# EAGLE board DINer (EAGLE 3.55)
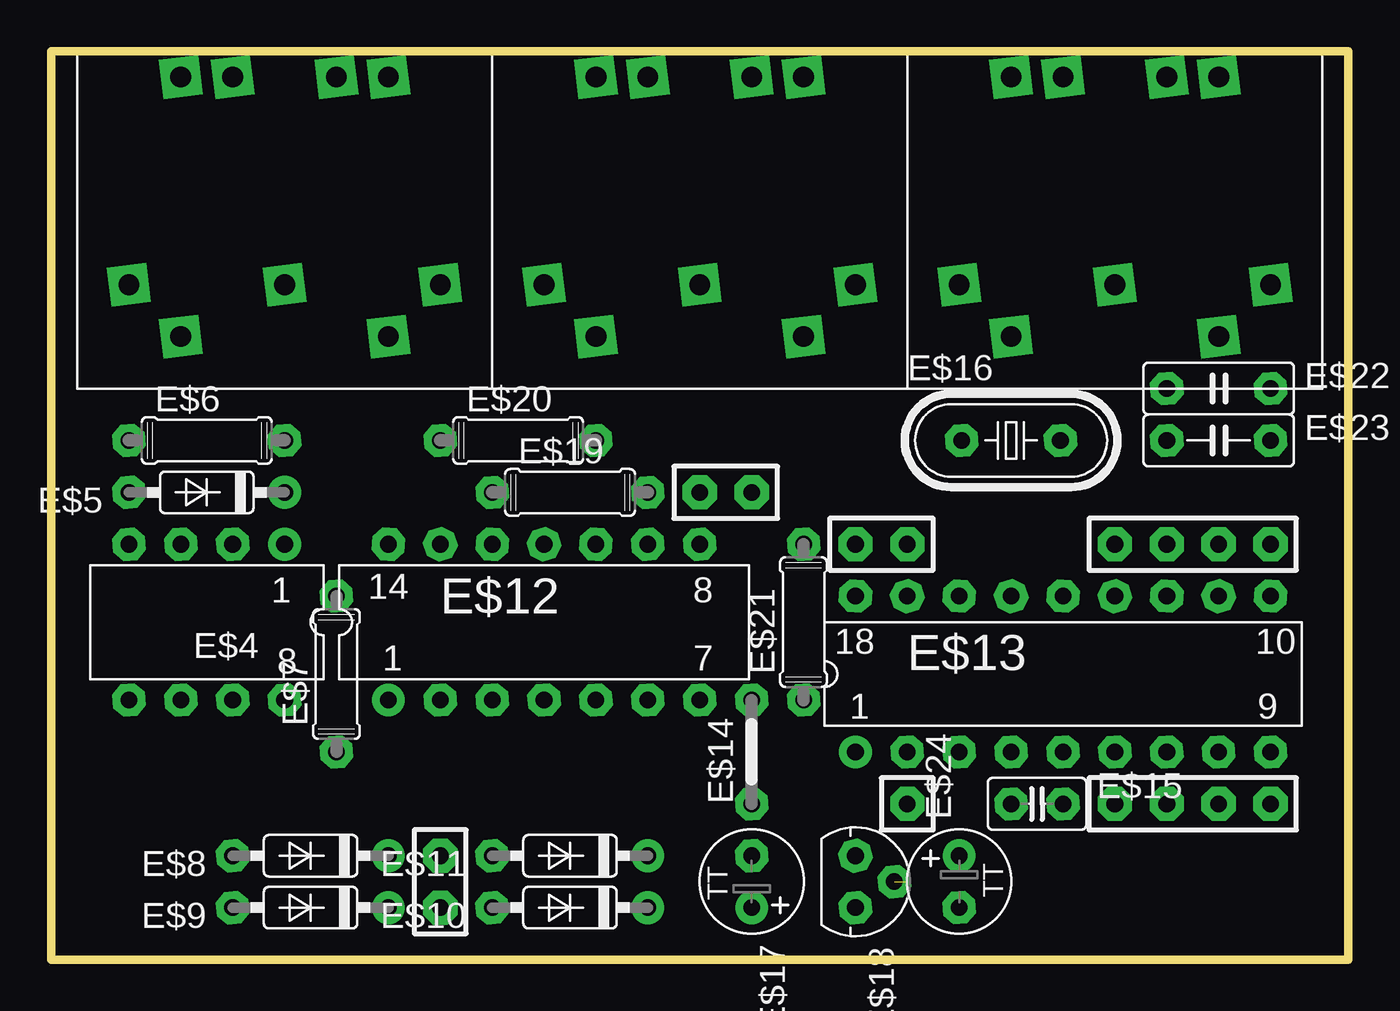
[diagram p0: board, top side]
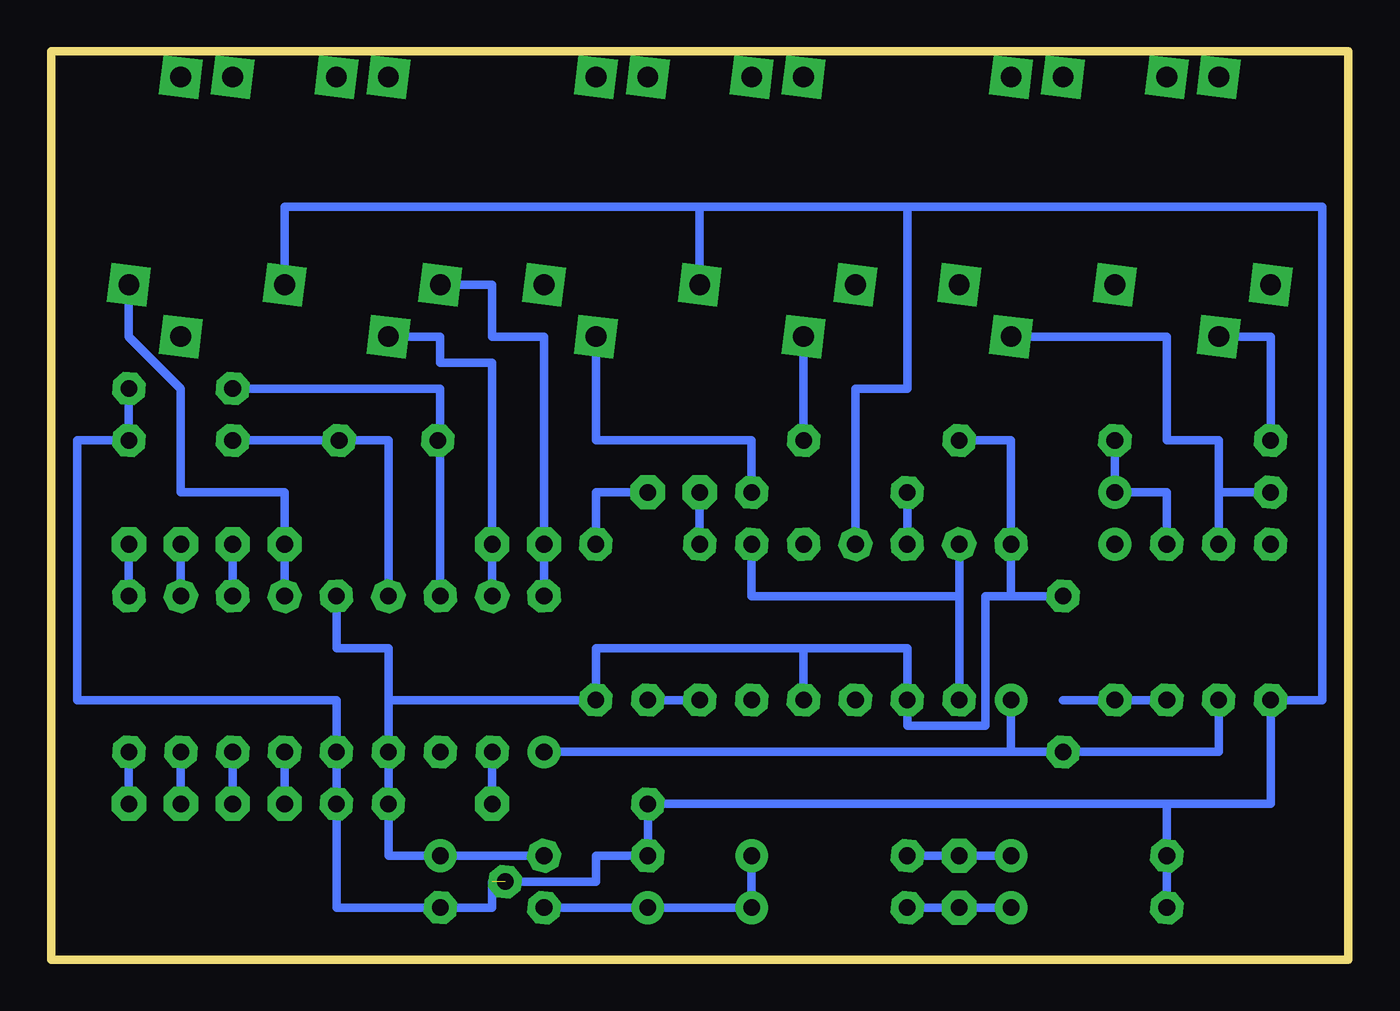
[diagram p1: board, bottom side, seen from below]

Size 63.5 x 44.45 mm. Coordinates in mm from the lower left corner, seen from the top.
Outline: 0,44.45 0,0 63.5,0 63.5,44.45 0,44.45
Copper layers used: Bottom

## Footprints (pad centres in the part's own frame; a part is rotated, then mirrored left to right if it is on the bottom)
_PCB = drill 1.016 pad 1.93 square:  -7.62,10.16;  -5.08,10.16;  0,10.16;  2.54,10.16;  -2.54,0;  -7.62,-2.54;  -10.16,0;  2.54,-2.54;  5.08,0
L08 = drill 0.813 pad 1.6 round:  -3.81,-3.81 | drill 0.813 pad 1.6 octagon:  -1.27,-3.81;  1.27,-3.81;  3.81,-3.81;  3.81,3.81;  1.27,3.81;  -1.27,3.81;  -3.81,3.81
35-7 = drill 0.813 pad 1.6 round:  -3.81,0 | drill 0.813 pad 1.6 octagon:  3.81,0
07/7 = drill 0.813 pad 1.6 octagon:  -3.81,0;  3.81,0
L14 = drill 0.813 pad 1.6 round:  -7.62,-3.81 | drill 0.813 pad 1.6 octagon:  -5.08,-3.81;  -2.54,-3.81;  0,-3.81;  2.54,-3.81;  5.08,-3.81;  7.62,-3.81;  7.62,3.81;  5.08,3.81;  2.54,3.81;  0,3.81;  -2.54,3.81;  -5.08,3.81;  -7.62,3.81
L18 = drill 0.813 pad 1.6 round:  -10.16,-3.81 | drill 0.813 pad 1.6 octagon:  -7.62,-3.81;  -5.08,-3.81;  -2.54,-3.81;  0,-3.81;  2.54,-3.81;  5.08,-3.81;  7.62,-3.81;  10.16,-3.81;  10.16,3.81;  7.62,3.81;  5.08,3.81;  2.54,3.81;  0,3.81;  -2.54,3.81;  -5.08,3.81;  -7.62,3.81;  -10.16,3.81
 = drill 0.813 pad 1.6 octagon:  -2.54,0;  2.54,0
,5-2 = drill 0.813 pad 1.6 octagon:  -1.27,0;  1.27,0
49U-V = drill 0.813 pad 1.6 octagon:  -2.413,0;  2.413,0
2D5 = drill 0.813 pad 1.6 octagon:  -1.27,0 | drill 0.813 pad 1.6 round:  1.27,0
92A = drill 0.813 pad 1.6 octagon:  -1.27,0;  0,1.905;  1.27,0
B2,5 = drill 0.813 pad 1.6 octagon:  -2.54,0;  2.54,0

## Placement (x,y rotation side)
E$1  DIN 5p  [_PCB]  13.97,33.02 0 top
E$2  DIN 5p  [_PCB]  34.29,33.02 0 top
E$3  DIN 5p  [_PCB]  54.61,33.02 0 top
E$4  6N137  [L08]  7.62,16.51 180 top
E$5  1N4148  [35-7]  7.62,22.86 180 top
E$6  220  [07/7]  7.62,25.4 0 top
E$7  360  [07/7]  13.97,13.97 90 top
E$8  1N4148  [35-7]  12.7,5.08 180 top
E$9  1N4148  [35-7]  12.7,2.54 180 top
E$10  1N4148  [35-7]  25.4,2.54 180 top
E$11  1N4148  [35-7]  25.4,5.08 180 top
E$12  74HC14  [L14]  24.13,16.51 0 top
E$13  PIC16F84/4MHz  [L18]  49.53,13.97 0 top
E$14  []  34.29,10.16 90 top
E$15  0.1  [,5-2]  48.26,7.62 0 top
E$16  4MHz  [49U-V]  46.99,25.4 0 top
E$17  47/16V  [2D5]  34.29,3.81 270 top
E$18  78L05  [92A]  39.37,3.81 270 top
E$19  220  [07/7]  25.4,22.86 0 top
E$20  220  [07/7]  22.86,25.4 0 top
E$21  1k  [07/7]  36.83,16.51 90 top
E$22  33p  [B2,5]  57.15,27.94 0 top
E$23  33p  [B2,5]  57.15,25.4 0 top
E$24  47/10V  [2D5]  44.45,3.81 90 top

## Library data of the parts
E$1-E$3 = con-din
E$4 = optocpl
E$5 E$8-E$11 = diode
E$6 E$7 E$19-E$21 = r
E$12 = 40xx
E$13 = pic
E$14 = JUMPER
E$15 E$22 E$23 = cap
E$16 = quartz
E$17 E$24 = cap-tant
E$18 = v-reg

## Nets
S$1: E$8. E$11.
S$2: E$9. E$10.
S$3: E$13.
S$4: E$13.
S$5: E$13.
S$6: E$13.
S$7: E$13.
S$8: E$3. E$13.
S$9: E$13. E$16. E$22.
S$10: E$13.
S$11: E$13.
S$12: E$13.
S$13: E$3. E$13.
S$14: E$12.
S$15: E$21.
S$16: E$1. E$6.
S$17: E$1. E$4. E$5.
S$18: E$12.
S$19: E$4. E$5. E$6.
S$20: E$7. E$12. E$13. E$15. E$18. E$20. E$21. E$24.
S$21: E$13. E$16. E$23.
S$23: E$2. E$19.
S$24: E$2. E$20.
S$25: E$12. E$19.
S$26: E$2. E$3. E$4. E$8. E$9. E$12. E$13. E$14. E$15. E$17. E$18. E$22. E$23. E$24.
S$27: E$4.
S$28: E$12. E$14.
S$30: E$3. E$13.
S$32: E$4. E$7. E$12. E$13.
S$34: E$10. E$11. E$17. E$18.

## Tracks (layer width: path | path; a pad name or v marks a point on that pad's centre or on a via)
S$1  (via drill 0.81 pad 1.68)
  Bottom 0.406: 16.51,5.08 v19.05,5.08 E$11.
S$2  (via drill 0.81 pad 1.68)
  Bottom 0.406: E$10. v19.05,2.54 16.51,2.54
S$3  (via drill 0.81 pad 1.68)
  Bottom 0.406: 52.07,10.16 v52.07,7.62
S$4  (via drill 0.81 pad 1.68)
  Bottom 0.406: v54.61,7.62 54.61,10.16
S$5  (via drill 0.81 pad 1.68)
  Bottom 0.406: 57.15,10.16 v57.15,7.62
S$6  (via drill 0.81 pad 1.68)
  Bottom 0.406: 59.69,10.16 v59.69,7.62
S$7  (via drill 0.81 pad 1.68)
  Bottom 0.406: 41.91,10.16 v41.91,7.62
S$8  (via drill 0.81 pad 1.68)
  Bottom 0.406: E$13. v39.37,20.32 39.37,30.48 41.91,30.48 41.91,33.02 44.45,33.02
S$9
  Bottom 0.406: 44.45,17.78 44.45,25.4 | 44.58,25.4 44.45,25.4 | 44.45,25.4 44.45,27.94 54.61,27.94
S$10  (via drill 0.81 pad 1.68)
  Bottom 0.406: 59.69,17.78 v59.69,20.32
S$11  (via drill 0.81 pad 1.68)
  Bottom 0.406: v57.15,20.32 57.15,17.78
S$12  (via drill 0.81 pad 1.68)
  Bottom 0.406: v54.61,20.32 54.61,17.78
S$13  (via drill 0.81 pad 1.68)
  Bottom 0.406: 52.07,17.78 v52.07,20.32 52.07,22.86 57.15,22.86 57.15,27.94 59.69,30.48 E$3.
S$14  (via drill 0.81 pad 1.68)
  Bottom 0.406: v31.75,22.86 31.75,20.32
S$15  (via drill 0.81 pad 1.68)
  Bottom 0.406: E$21. 36.83,22.86 v34.29,22.86
S$16
  Bottom 0.406: 6.35,30.48 3.81,30.48 3.81,25.4
S$17
  Bottom 0.406: 6.35,22.86 E$5. | 6.35,20.32 6.35,22.86 | 16.51,30.48 8.89,30.48 8.89,25.4 6.35,25.4 6.35,22.86
S$18
  Bottom 0.406: 19.05,20.32 19.05,17.78 | 29.21,20.32 29.21,17.78 19.05,17.78 | 19.05,12.7 19.05,17.78
S$19
  Bottom 0.406: E$6. 11.43,22.86 8.89,22.86 8.89,20.32
S$20
  Bottom 0.406: 26.67,15.24 26.67,12.7 | 19.05,25.4 16.51,25.4 E$12. 16.51,17.78 | 26.67,15.24 21.59,15.24 21.59,12.7 21.59,11.43 17.78,11.43 17.78,17.78 16.51,17.78 | 16.51,17.78 E$7. | 26.67,15.24 36.83,15.24 36.83,12.7 46.99,12.7 | 49.53,17.78 49.53,15.24 46.99,15.24 46.99,12.7 | 46.99,12.7 46.99,10.16 46.99,7.62 46.99,5.08 E$24. 39.37,5.08
S$21
  Bottom 0.406: 54.61,25.4 E$16. 46.99,25.4 46.99,17.78
S$23
  Bottom 0.406: E$19. 29.21,25.4 36.83,25.4 36.83,30.48
S$24
  Bottom 0.406: 26.67,30.48 E$20.
S$25
  Bottom 0.406: 21.59,22.86 21.59,20.32
S$26  (1 unrouted)
  Bottom 0.406: 24.13,20.32 24.13,27.94 21.59,27.94 21.59,36.83 | 52.07,33.02 52.07,36.83 31.75,36.83 | 31.75,36.83 31.75,33.02 | 21.59,36.83 31.75,36.83 | 21.59,36.83 1.27,36.83 1.27,12.7 3.81,12.7 3.81,7.62 8.89,7.62 | 8.89,7.62 E$8. E$9. | 8.89,7.62 34.29,7.62 34.29,5.08 36.83,5.08 36.83,3.81 41.27,3.81 41.91,3.81 41.91,2.54 44.45,2.54 49.53,2.54 E$15. 49.53,10.16 49.53,12.7 62.23,12.7 62.23,25.4 E$23. E$22.
S$27
  Bottom 0.406: 13.97,12.7 E$4. 8.89,12.7
S$28
  Bottom 0.406: 31.75,12.7 E$14.
S$30  (via drill 0.81 pad 1.68)
  Bottom 0.406: 46.99,30.48 44.45,30.48 44.45,29.21 41.91,29.21 v41.91,20.32 41.91,17.78
S$32
  Bottom 0.406: 6.35,12.7 6.35,10.16 13.97,10.16 16.51,10.16 | 16.51,10.16 16.51,12.7 | 16.51,10.16 39.37,10.16
S$34
  Bottom 0.406: E$18. E$17. 29.21,2.54 29.21,5.08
